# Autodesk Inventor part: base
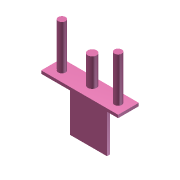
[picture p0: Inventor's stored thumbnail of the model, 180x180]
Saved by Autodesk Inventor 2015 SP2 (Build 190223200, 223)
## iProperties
Created: 2020-09
Part Number: base
Material: 一般
Document SubType Name: Modeling
Designer: Kuan_Lun Hsu
Density: 1 g/cm^3
Appearance: 預設
Author: Kuan_Lun Hsu
Author: IANNIAN
Title: D:\Desktop\OCW-Computer-Aided Engineering Drawing\OCW_Topic 06：組合圖與機構模擬(進階)\6-1_Flexibility\Mechanical Gripper(piston)\Mechanical Gripper(STP)\base.stp
Creation Date: 2020-09-04
Sending System: Autodesk Inventor 2020
Preprocessor: ST-DEVELOPER v18
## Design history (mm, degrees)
node "base2"
body "Solid2"
node "Base1"
